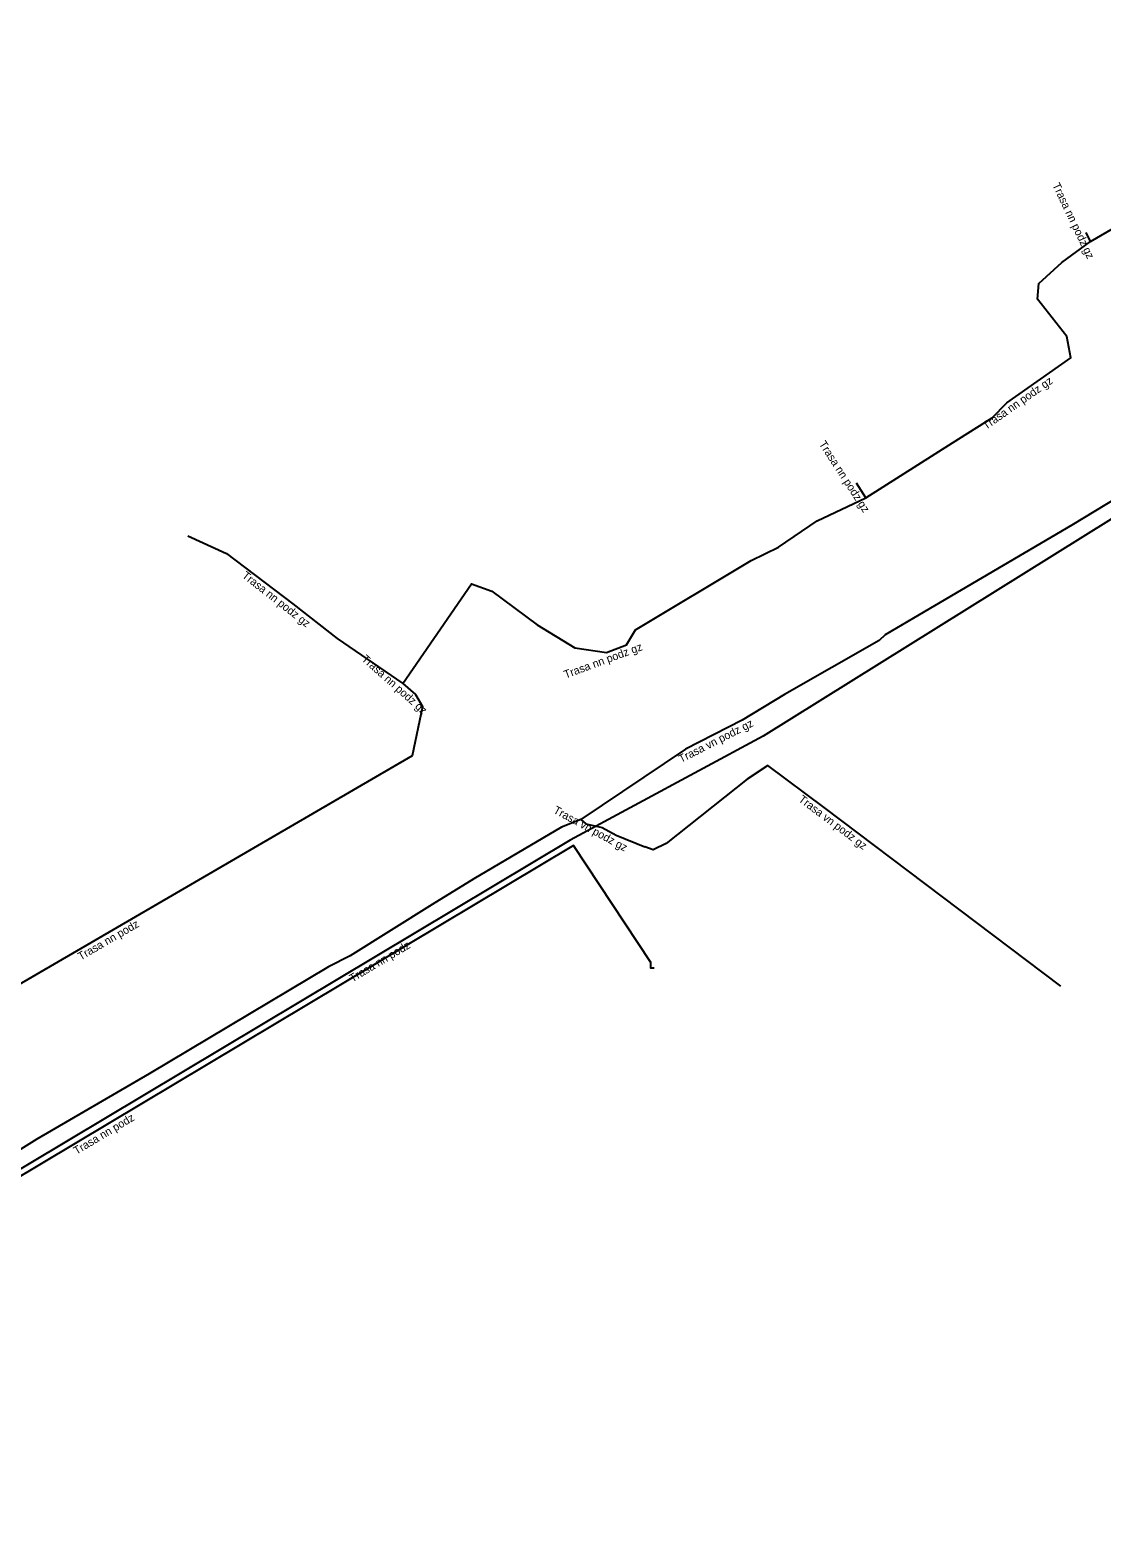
# Model space of a CAD drawing. Extents: x -689216 to -688745, y -973188 to -972893.
# Drawn here: x -689015.2 to -688948.2, y -973092.7 to -972998.8 of the extents above; entities that cross this region are included whole.
import ezdxf

# ---------------------------------------------------------------- set-up
doc = ezdxf.new("R2010")
doc.units = 0
for name, color, linetype in [('Popiskový text - Ostatní atributy Trasy', 7, 'Continuous'), ('Spojnice NN', 7, 'Continuous'), ('Spojnice VN', 7, 'Continuous')]:
    doc.layers.add(name, color=color, linetype=linetype)

msp = doc.modelspace()

# ---------------------------------------------------------------- linework, layer by layer
at = {"layer": 'Spojnice NN'}
for points in [[(-688948.94, -973012.04), (-688940.11, -973006.92), (-688926.19, -972998.83)], [(-688948.94, -973012.04), (-688949.21, -973011.47)], [(-688962.96, -973028.06), (-688957.55, -973024.63), (-688955.07, -973023.05), (-688954.17, -973022.12), (-688950.17, -973019.3), (-688950.41, -973017.97), (-688952.25, -973015.65), (-688952.16, -973014.66), (-688950.72, -973013.35), (-688948.94, -973012.04)], [(-688962.96, -973028.06), (-688963.55, -973027.15)], [(-688991.88, -973039.65), (-688987.61, -973033.43), (-688986.34, -973033.88), (-688983.49, -973035.99), (-688981.14, -973037.42), (-688979.16, -973037.71), (-688977.92, -973037.25), (-688977.35, -973036.31), (-688970.12, -973031.98), (-688968.42, -973031.14), (-688966.01, -973029.49), (-688962.96, -973028.06)], [(-688947.649, -973029.398), (-688969.376, -973042.94), (-688981.428, -973049.441), (-689024.998, -973075.491), (-689031.279, -973079.019), (-689037.83, -973082.74)], [(-689005.31, -973030.44), (-689002.9, -973031.54), (-688998.77, -973034.68), (-688996, -973036.85), (-688991.88, -973039.65)], [(-688991.88, -973039.65), (-688991.09, -973040.35), (-688990.66, -973041.1)], [(-688990.66, -973041.1), (-688991.304, -973044.169), (-689024.753, -973063.633), (-689027.871, -973058.485), (-689028.364, -973058.819), (-689028.252, -973058.985)], [(-688976.198, -973057.433), (-688976.398, -973057.433), (-688976.398, -973057.077), (-688981.222, -973049.785), (-689024.798, -973075.837), (-689031.085, -973079.369), (-689036.902, -973082.673), (-689035.997, -973084.002), (-689034.132, -973087.481), (-689032.882, -973090.186), (-689032.62, -973092.042), (-689032.843, -973092.665), (-689033.22, -973092.53)]]:
    msp.add_lwpolyline(points, dxfattribs=at)
at = {"layer": 'Spojnice VN'}
for points in [[(-688947.24, -973028.03), (-688950.11, -973029.76), (-688960, -973035.58), (-688961.77, -973036.61)], [(-688961.77, -973036.61), (-688962.14, -973036.97), (-688968.04, -973040.34), (-688970.69, -973041.95), (-688974.24, -973043.76), (-688980.78, -973048.15)], [(-688950.777, -973058.561), (-688965.57, -973047.41), (-688969.08, -973044.77), (-688970.39, -973045.64), (-688975.43, -973049.65), (-688976.25, -973050.05), (-688976.78, -973049.86)], [(-688980.78, -973048.15), (-688981.98, -973048.64), (-688987.46, -973051.87), (-688990.06, -973053.46), (-688995.17, -973056.67), (-688996.53, -973057.36), (-689007.73, -973064.05), (-689014.76, -973068.12), (-689019.77, -973071.25), (-689024.55, -973074), (-689029.25, -973076.87), (-689034.56, -973079.99), (-689039.88, -973083), (-689040.5, -973083.45), (-689040.85, -973083.83), (-689041.5, -973083.83), (-689045.47, -973077.68), (-689045.6, -973077.3), (-689046.68, -973075.25), (-689047.96, -973073.01), (-689049.506, -973070.395)], [(-688980.78, -973048.15), (-688980.45, -973048.42), (-688979.44, -973048.66), (-688978.56, -973049.14), (-688976.78, -973049.86)]]:
    msp.add_lwpolyline(points, dxfattribs=at)

# ---------------------------------------------------------------- texts
at = {"layer": 'Popiskový text - Ostatní atributy Trasy'}
for s, rotation, p in [('Trasa nn podz gz', 295.34618, (-688951.329, -973008.514)), ('Trasa nn podz gz', 35.18384, (-688955.458, -973023.824)), ('Trasa nn podz gz', 302.95742, (-688965.919, -973024.692)), ('Trasa nn podz gz', 321.92508, (-689001.975, -973032.995)), ('Trasa nn podz gz', 318.45662, (-688994.507, -973038.191)), ('Trasa nn podz gz', 20.35323, (-688981.72, -973039.353)), ('Trasa vn podz gz', 27.01518, (-688974.509, -973044.627)), ('Trasa vn podz gz', 331.38954, (-688982.53, -973047.715)), ('Trasa vn podz gz', 322.99061, (-688967.217, -973046.983)), ('Trasa nn podz', 30.19516, (-689012.012, -973056.971)), ('Trasa nn podz', 30.87472, (-688995.042, -973058.338)), ('Trasa nn podz', 30.87318, (-689012.276, -973069.108))]:
    msp.add_text(s, height=0.5, rotation=rotation, dxfattribs=at).set_placement(p)

doc.saveas('drawing.dxf')
